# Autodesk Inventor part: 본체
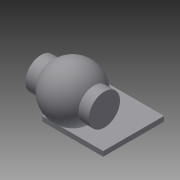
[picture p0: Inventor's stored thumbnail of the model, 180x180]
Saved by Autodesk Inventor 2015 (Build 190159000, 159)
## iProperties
Created: 2025-08
Part Number: 본체
Material: 일반
Document SubType Name: Modeling
Designer: USER
Density: 1 g/cm^3
Appearance: 기본값
Author: USER
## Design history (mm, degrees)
sketch "스케치1"
  geometry: L1 (-62.5, 62.5)-(62.5, 62.5); L2 (62.5, 62.5)-(62.5, -62.5); L3 (62.5, -62.5)-(-62.5, -62.5); L4 (-62.5, -62.5)-(-62.5, 62.5); L5 (-62.5, 62.5)-(62.5, -62.5); L6 (62.5, 62.5)-(-62.5, -62.5); 1 further point
  constraints: 12 end point, 2 midpoint, 2 parallel, 1 horizontal, 1 perpendicular
  dimensions: "d0" = 125 distance of L2.end L3.end; "d1" = 125 distance of L1.end L2.end
extrude "돌출1" new body sketch "스케치1" distance "d2" = 10; taper "d3" = 0 deg
sketch "스케치2"
  geometry: L1 (62.5, 0)-(62.5, 85); L2 (-2.5, 85)-(127.5, 85); L3 (-2.5, 85)-(-2.5, 96.019); L4 (127.5, 85)-(127.5, 96.026); L5 (-2.5, 85)-(-2.5, 53); L6 (-2.5, 53)-(19.003, 53); L7 (127.5, 85)-(127.5, 53); L8 (127.5, 53)-(105.997, 53); L9 (0, 0)-(125, 0) reference; A1 r 54 centre (62.5, 85) between (19.003, 53) and (105.997, 53); A2 r 44 centre (62.5, 85) between (18.5, 85) and (106.5, 85)
  constraints: 16 end point, 5 vertical, 4 point on circle, 2 centre point, 2 coincident, 2 horizontal, 1 perpendicular
  dimensions: "d4" = 85 distance of L1.start L1.end; "d5" = 108 diameter of A1; "d6" = 88 diameter of A2; "d7" = 130 distance of L2.start L2.end; "d10" = 32 distance of L2.end L7.end; "d11" = 85 distance from line of L9 L2.end; "d12" = 32 distance of L2.start L5.end; "d13" = 21.50287 distance of L6.end L5.end
revolve "회전1" sketch "스케치2" stored, may be unused: angle "d14" = 90 deg
node "솔리드1"
